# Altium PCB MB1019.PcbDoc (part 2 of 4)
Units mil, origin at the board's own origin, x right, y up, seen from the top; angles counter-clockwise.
Board outline 4655 x 6805 mil, 4 copper layers (TopLayer, VCC, GND, BottomLayer), stack 26.137 mil thick; 557 components, 425 nets, 1918 pads, 817 vias.
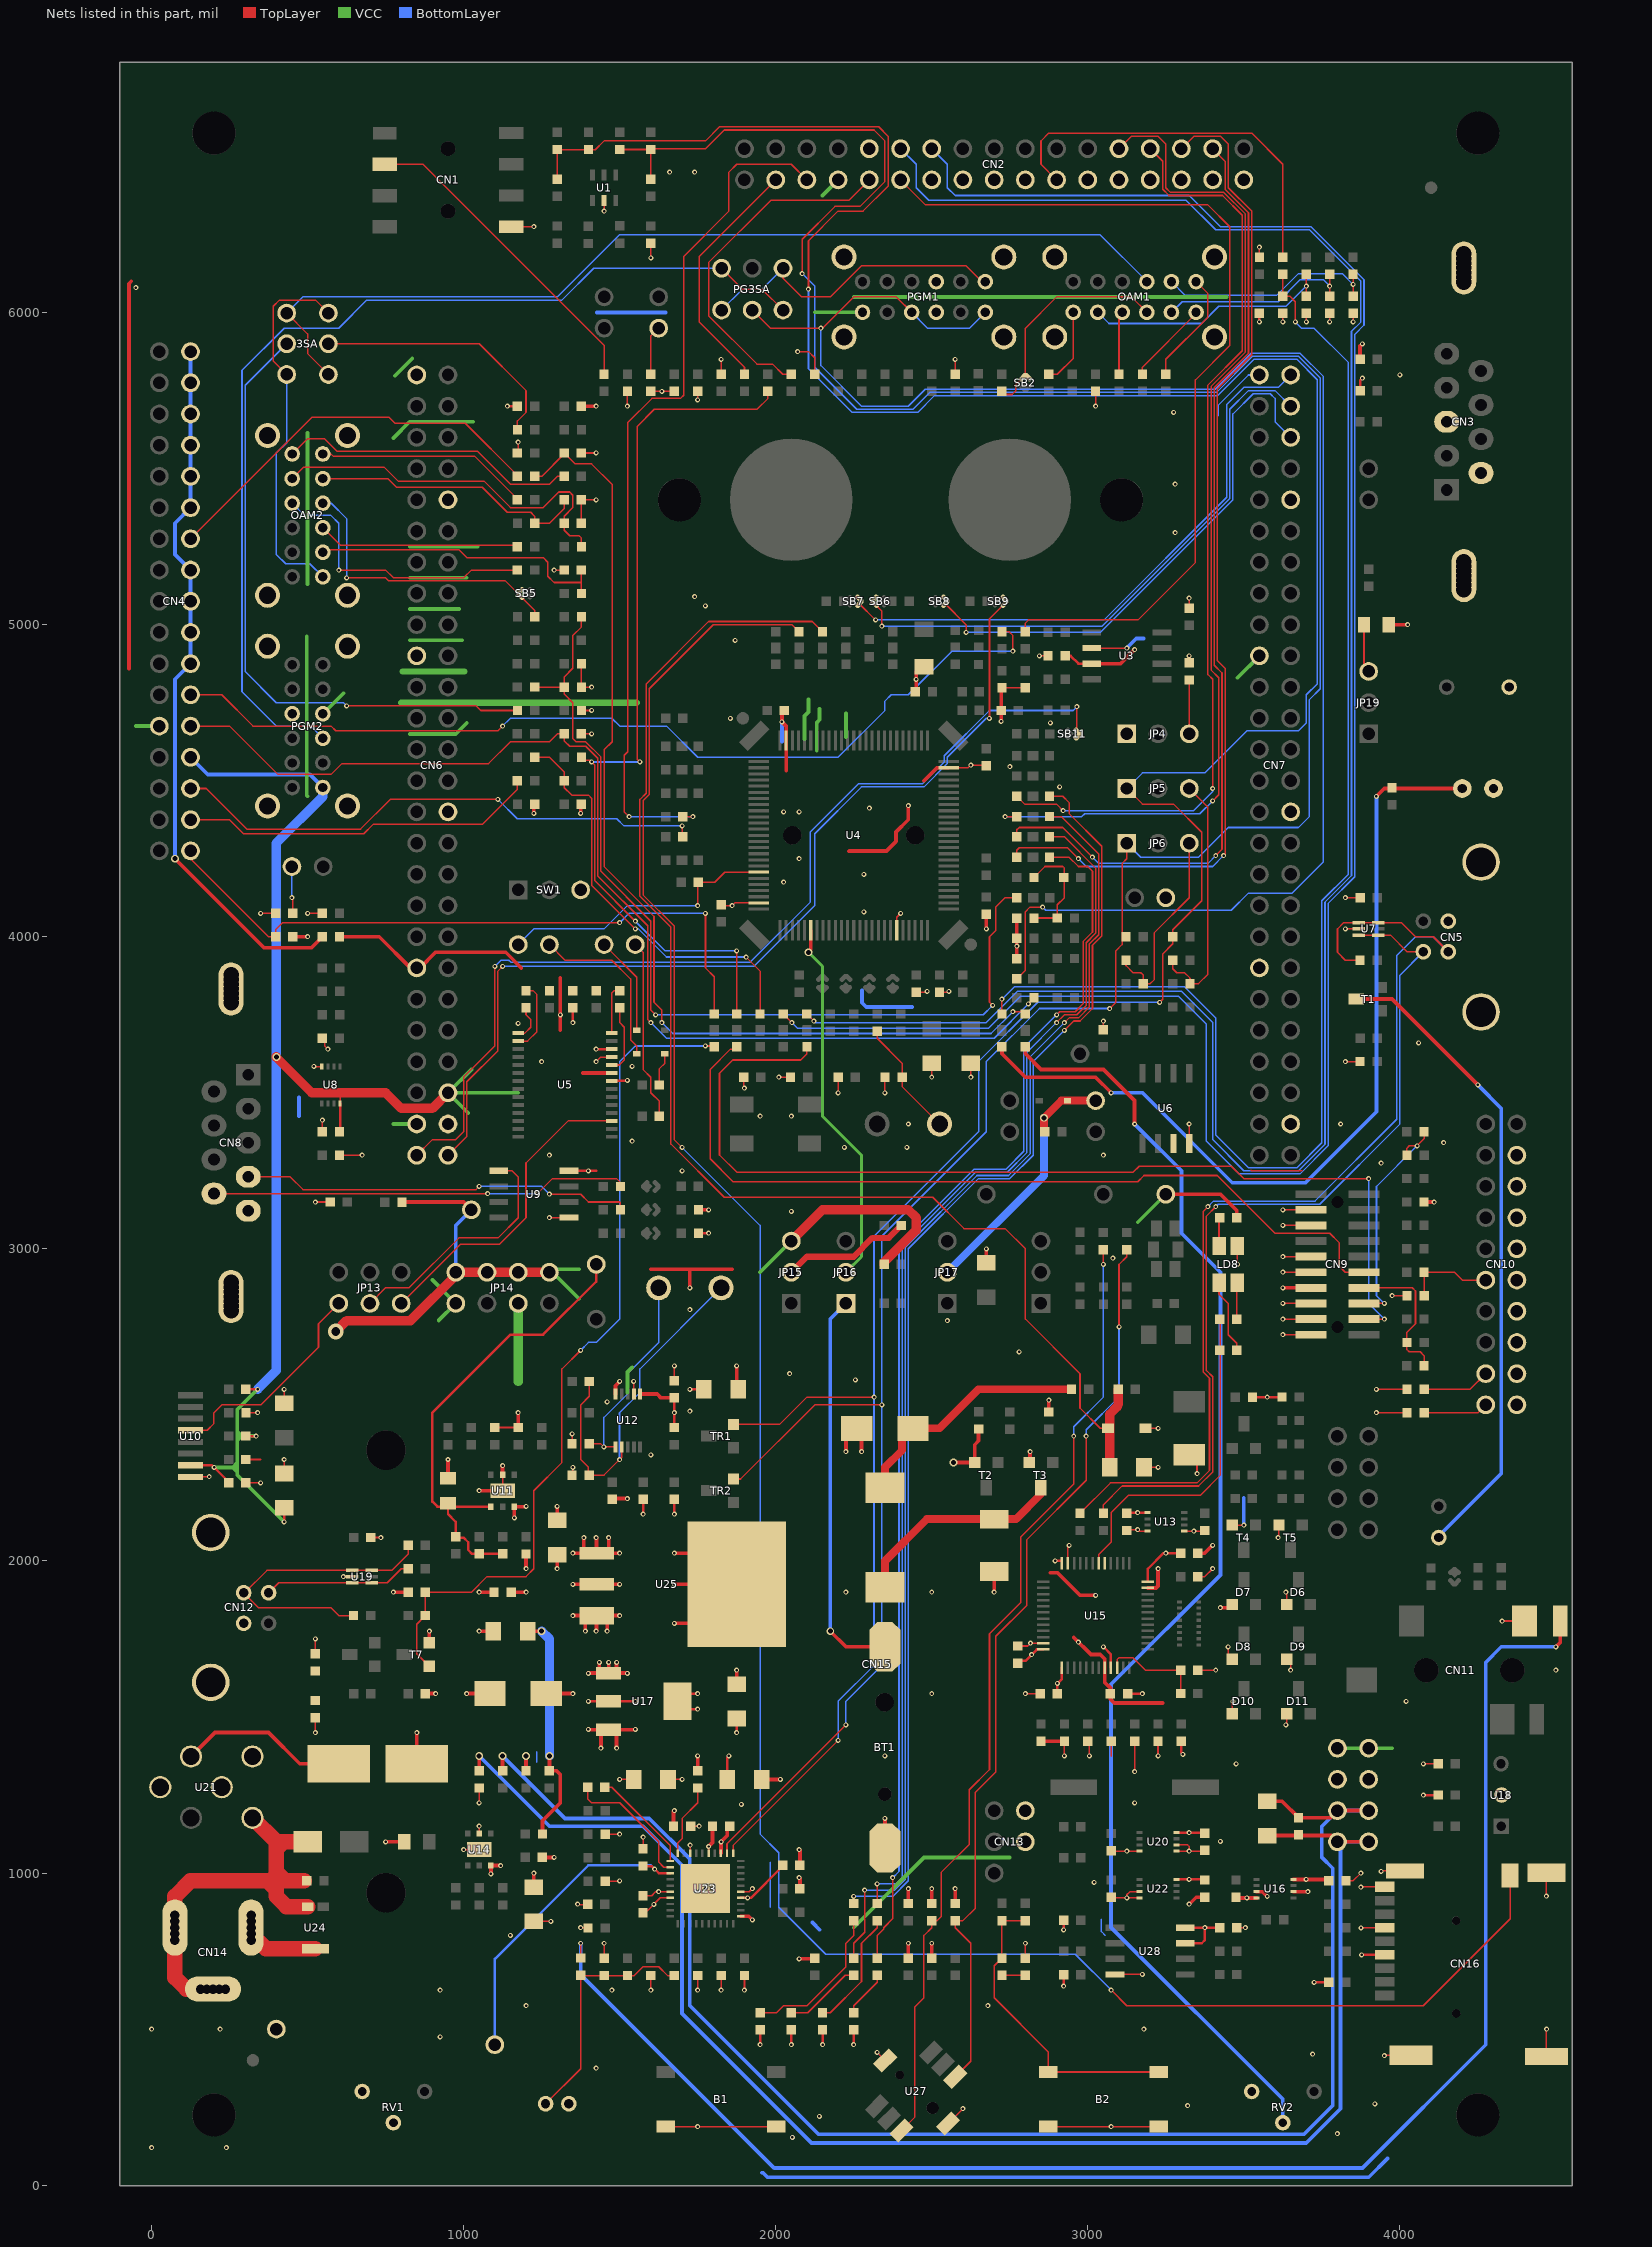
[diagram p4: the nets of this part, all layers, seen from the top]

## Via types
v1: diameter 16, hole 8, TopLayer to BottomLayer, tented both sides, 770 vias
v2: diameter 16, hole 8, TopLayer to BottomLayer, 26 vias
v3: diameter 25, hole 16, TopLayer to BottomLayer, tented both sides, 17 vias
v4: diameter 50, hole 28, TopLayer to BottomLayer, tented both sides, 4 vias

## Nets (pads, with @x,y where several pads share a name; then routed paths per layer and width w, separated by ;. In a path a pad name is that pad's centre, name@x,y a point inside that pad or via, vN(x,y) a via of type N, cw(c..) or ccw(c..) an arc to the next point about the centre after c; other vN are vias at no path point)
+1V8: C66.1 C70.2 R253.2 R278.1 TP6.1 U11.4 | length 1527.4
  TopLayer w7.87: C66.1@950,2173.82 950,2150 975,2125 975,2077.5 977.5,2075 1000,2075 1015,2060 1015,2035 1027.5,2022.5 C70.2@1125,2022.5 ; U11.4@1087.6,2173.82 916.18,2173.82 900,2190 900,2475 1150,2725 1255,2725 1425,2895 TP6.1@1425,2950
+2V5: C96.1 C103.1 C104.1 C105.1 C106.1 TP9.1 U17.2 U23.13 U23.16 U23.34 | length 1686.9
  TopLayer w5: C105.1@1575,927.5 1602.5,927.5 1615.16,940.16 U23.16@1662.01,940.16
  TopLayer w8: v1(1400,1550) v1(1550,1550) ; C106.1@1575,1022.5 1602.5,1022.5 1625.79,999.21 U23.13@1662.01,999.21 ; U17.2@1685,1525 v1(1750,1525) ; U17.2@1685,1575 v1(1750,1575) ; C96.1@1845,1300 1845,1370 v1(1850,1375) ; v1(1875,1450) C104.1@1875,1495 ; U23.34@1887.99,920.47 1920.47,920.47 2022.5,1022.5 C103.1@2022.5,1025
  BottomLayer w8: TP9.1@1100,450 1100,725 1400,1025 1600,1025 v1(1612.32,1012.68)
  other v1: 1910,920.47 1625,940.16
+3V3: C18.2 C36.2 C53.2 C57.1 C60.1 C65.1 C69.1 C74.2 C76.2 C80.2 C82.1 C83.1 C84.2 C86.1 C110.2 C114.1 C115.2 C129.2 CN2.28 CN4.28 CN6.48 CN13.4 CN15.9 CN15.10 CN16.4 JP15.3 LD1.1 LD2.1 LD3.1 LD4.1 LD9.1 PGM1.1 PGM1.4 PGM1.7 PGM2.1 PGM2.4 PGM2.7 R72.2 R78.2 R86.1 R125.2 R222.2 R228.2 R230.2 R240.2 R243.1 R249.2 R252.1 R255.1 R269.1 R270.1 R277.2 R292.2 R293.1 R296.2 R314.1 R320.2 R328.1 T1.3 TP4.1 U3.3 U5.22 U5.26 U8.8 U9.8 U10.7 U12.1 U13.1 U15.1 U15.9 U15.24 U15.36 U15.48 U16.8 U20.8 U22.8 U25.2 U28.7 U28.8 | length 16163.7
  TopLayer w5: U8.8@604.53,3465.94 604.53,3499.53 605,3500
  TopLayer w8: U10.7@125,2306.5 193.5,2306.5 247.5,2252.5 C65.1@247.5,2250 ; R252.1@302.5,2400 v1(335,2400) ; R243.1@302.5,2550 v1(340,2550) ; v1(425,2125) C69.1@425,2170 ; C53.2@604.53,3377.03 U8.8@604.53,3465.94 ; v1(1140,5700) R78.2@1172.5,5700 ; U9.8@1337.5,3250 1425,3250 ; v1(1350,3725) C36.2@1350,3772.5 ; v1@1425.16,3640.16 U5.26@1474.61,3640.16 ; U5.22@1474.61,3537.8 1522.8,3537.8 v1(1525,3540) ; v1@1576,2151 R269.1@1576,2197.5 ; v1(1675,2150) R270.1@1675,2197.5 ; R255.1@1675,2427.5 C60.1@1675,2522.5 ; v1(1725,2550) C57.1@1770,2550 ; R230.2@1752.5,3050 v1(1785,3050) ; v1(1950,450) LD4.1@1950,497.5 ; v1(2050,450) LD3.1@2050,497.5 ; v1(2150,450) LD2.1@2150,497.5 ; v1(2250,450) LD1.1@2250,497.5 ; C80.2@2770,1680 2800,1680 2836.73,1716.73 U15.48@2857.68,1716.73 ; v1(2895,2000) U15.36@2915,2000 ; C82.1@2902.5,1575 v1(2902.5,1607.5) 2916.73,1621.73 U15.1@2916.73,1657.68 ; v1(2922.5,637.5) R328.1@2922.5,674 ; v1(2922.5,817.5) R314.1@2922.5,849 ; C18.2@2927.5,4900 2945,4900 2970,4875 U3.3@3012.5,4875 ; v1(3050,1725) 3074.21,1700.79 U15.9@3074.21,1657.68 ; C76.2@3127.03,2154.53 U13.1@3190.94,2154.53 ; C84.2@3127.5,1575 v1(3175,1575) ; U15.24@3192.32,1933.27 3192.32,1975 3242.32,2025 C74.2@3297.5,2025 ; U22.8@3284.06,979.53 C115.2@3372.97,979.53 ; U20.8@3284.06,1129.53 C110.2@3372.97,1129.53 ; R292.2@3300,1422.5 3300,1385 v1(3305,1380) ; U28.7@3312.5,775 3365,775 3375,785 v1(3375,825) ; U28.8@3312.5,825 C114.1@3422.5,825 ; R249.2@3527.5,2525 R240.2@3622.5,2525 ; v1(3550,5970) R72.2@3550,5997.5 ; v1(3725,650) R320.2@3772.5,650 ; R86.1@3872.5,5750 3872.5,5782.5 v1(3880,5790) ; v1(3877.01,737.99) CN16.4@3951.65,737.99 ; v1(4075,1250) R296.2@4122.5,1250
  TopLayer w12: C86.1@1152.5,1900 v1(1200,1900) ; C83.1@1205,1775 v3(1250,1775) ; R277.2@1252.5,1125 1252.5,1167.5 1310,1225 1310,1315 1297.5,1327.5 1275,1327.5 v3(1275,1375) ; v1(1350,1925) v1(1500,1925) ; U12.1@1565.37,2534.69 1620.31,2534.69 1632.5,2522.5 C60.1@1675,2522.5 ; v1(1675,1800) U25.2@1760,1800 ; v1(1675,1925) U25.2@1780,1925 ; v1(1675,2025) U25.2@1765,2025 ; U3.3@3012.5,4875 3105,4875 v1(3150,4920) ; TP4.1@3250,3175 3425,3175 3477.5,3122.5 R228.2@3477.5,3100 ; R125.2@3325,4877.5 v1(3325,4900) ; U16.8@3659.06,979.53 3767.97,979.53 C129.2@3772.5,975 ; T1.3@3860,3800.5 3974.5,3800.5 v1(4250,3525)
  TopLayer w30: v3(400,3615) 400,3613.54 513.54,3500 750,3500 800,3450 900,3450 CN6.48@950,3500 ; JP15.3@2050,3025 2150,3125 2425,3125 2450,3100 2450,3060 2347.5,2957.5 R222.2@2347.5,2950
  VCC w12: v1(200.24,2299.76) 260.24,2299.76 275,2285 ; 275,2300 260,2300 275,2315 ; 275,2400 290,2400 ; v1(335,2400) 290,2400 ; v1(340,2550) 275,2485 275,2415 ; v1(425,2125) 275,2275 275,2385 ; 497.38,4962.38 497.38,4452.62 500,4450 ; 500,5130 500,5615 ; PGM2.4@549.21,4714.37 614.84,4780 ; 775,5597.91 827.09,5650 1030,5650 ; 780.09,5797.46 835.76,5853.12 ; 827.09,4950 995,4950 ; 827.09,5050 985,5050 ; 827.09,5150 1010,5150 ; 827.09,5250 1045,5250 ; 1015,3435 CN6.48@950,3500 ; 1025,3575 CN6.48@950,3500 ; 1175,3500 CN6.48@950,3500 ; 1950,2925 JP15.3@2050,3025 ; JP15.3@2050,3020 JP15.3@2060,3020 ; 2125.79,6000.79 PGM1.1@2278.15,6000.79 ; 2150,6375 CN2.28@2200,6425 ; 2250,825 2475,1050 2750,1050 ; 2250,6050 3445,6050 ; 3160,3085 TP4.1@3250,3175 ; CN15.9@3800,1400 3975,1400 ; 275,2385 275,2415 ; 275,2385 290,2400 ; 275,2415 290,2400
  BottomLayer w12: CN4.28@125,4575 180,4520 507.36,4520 PGM2.1@549.21,4478.15 ; LD9.1@4125,2075 4120,2075 4325,2280 4325,3450 v1(4250,3525)
  BottomLayer w30: v1(340,2550) 400,2610 400,4300 549.21,4449.21 PGM2.1@549.21,4478.15 ; v3(1250,1775) 1275,1750 v3(1275,1375)
  other v1: 3325,979.53 3325,1129.53 2819.78,1699.78 3250,2025 1575,2150 3160,2154.53 1675,2475 3575,2525 1400,3250 1425,3640
  other v2: 3699.53,979.53
+5V: C67.1 C78.1 C87.1 C91.1 C94.1 C99.1 CN2.25 CN4.25 JP14.2 JP14.4 JP14.6 JP14.8 R225.2 R258.1 R290.1 T3.1 TP5.1 U11.6 U14.6 U17.3 U23.5 U23.8 U25.3 | length 2799.6
  TopLayer w5: R225.2@802.5,3150 R225.2@815,3150 ; C91.1@1655,1300 v1(1700,1300) ; U23.8@1725.79,1062.99 v1(1725.79,1089.21) ; C94.1@1727.5,1150 v1(1755,1150) ; U23.5@1784.84,1062.99 v1@1784.84,1084.84
  TopLayer w12: R225.2@815,3150 1000,3150 TP5.1@1025,3125 ; v1(1087.4,997.6) U14.6@1087.4,1023.82 v1(1118.82,1023.82) ; v1(1162.4,2137.6) U11.6@1162.4,2173.82 v1@1198.82,2173.82 ; R290.1@1200,1327.5 v3(1200,1375) ; C78.1@1225,955 v1(1225,1000) ; C87.1@1265,1575 v1(1350,1575) ; C67.1@1300,2130 v1(1300,2175) ; v1(1350,1825) v1(1500,1825) ; v1(1390,1775) U25.3@1390,1825 ; v1(1400,1460) 1400.55,1459.45 1549.45,1459.45 v1(1550,1460) ; v1(1425,1775) 1426.18,1776.18 U25.3@1426.18,1825 ; v1(1440,1400) U17.3@1440,1459.45 ; v1(1460,1775) U25.3@1460,1825 ; v1(1490,1400) U17.3@1490,1459.45 ; v1(1785,1085) 1797.5,1097.5 C99.1@1797.5,1150 ; T3.1@2815,2315 v1(2815,2350) ; R258.1@2875,2477.5 v1(2875,2515)
  TopLayer w30: v4(590,2735) 625,2770 830,2770 JP14.2@985,2925 ; JP14.2@975,2925 JP14.8@1275,2925
  VCC w12: -50,4675 CN4.25@25,4675 ; JP14.8@1275,2925 1285,2925 1370,2840 ; JP14.8@1275,2935 1370,2935 ; 1525,2540 1525,2605 1540,2620
  BottomLayer w12: JP14.2@975,2925 975,3075 TP5.1@1025,3125
  other v1: 1200,2175
AIN_1: R287.1 R288.2 U15.10 | length 323.9
  TopLayer w5: U15.10@3093.9,1657.68 3093.9,1683.9 3100,1690 3145,1690 3185,1650 3297.5,1650 R288.2@3297.5,1575
BOOT0: JP9.2 R166.1 U4.94 | length 908.4
  TopLayer w5: v1(1750,4100) R166.1@1750,4172.5 ; R166.1@1752.5,4172.5 1752.5,4175 1805,4175 1836.89,4206.89 U4.94@1945.87,4206.89
  BottomLayer w5: JP9.2@1175,3975 1225,4025 1450,4025 1525,4100 v1(1750,4100)
D5V: CN6.49 CN7.19 JP14.1 | length 1852.3
  VCC w12: 775,3400 CN6.49@850,3400 ; 827.09,4650 975,4650 1010,4685 ; 900,2900 JP14.1@975,2825 920,2770 ; 2092.42,4632.58 2092.42,4707.42 2105,4720 2105,4760 ; 2131.89,4596.89 2131.89,4686.89 2140,4695 2140,4730 ; 2225,4640 2225,4715 ; 3480,4830 CN7.19@3550,4900
  VCC w20: 800,4750 1555,4750 ; 805,4850 1002.91,4850
E5V: C85.1 JP14.5 U21.3 | length 824.7
  TopLayer w12: U21.3@126.57,1373.43 203.15,1450 375,1450 475,1350 C85.1@600,1350
  VCC w12: U21.3@126.57,1373.43 U21.3@126.57,1401.57
  VCC w30: 1175,2575 JP14.5@1175,2825
GND: B1.1 B1.4 B2.1 B2.4 BT1.2 C1.1 C2.1 C3.2 C4.1 C5.1 C6.1 C7.1 C8.1 C9.1 C10.1 C11.1 C12.1 C13.1 C14.2 C15.1 C16.1 C17.1 C18.1 C19.1 C20.2 C22.1 C23.1 C24.1 C25.2 C26.1 C27.1 C28.1 C30.2 C31.1 C32.2 C34.1 C35.1 C36.1 C38.1 C39.1 C40.1 C42.2 C43.2 C45.2 C46.2 C47.2 C48.2 C49.1 C50.2 C51.2 C52.1 C53.1 C57.2 C58.2 C59.2 C60.2 C61.2 C62.2 C63.2 C64.2 C65.2 C66.2 C67.2 C68.2 C69.2 C71.2 C72.2 C73.2 C74.1 C75.2 C76.1 C78.2 C79.1 C80.1 C81.2 C82.2 C83.2 C84.1 C85.2 C86.2 C87.2 C88.1 C89.1 C90.2 C91.2 C92.1 C94.2 C95.2 C96.2 C99.2 C103.2 C104.2 C105.2 C106.2 C107.2 C108.1 C109.1 C110.1 C111.1 C112.1 C113.1 C114.2 C115.1 C116.1 C117.2 C118.2 C120.2 C121.1 C122.1 C124.1 C125.1 C126.1 C127.1 C128.1 C129.1 C130.1 C131.2 C132.2 C133.2 C134.2 C135.2 C136.2 CN1.7 CN2.2 CN2.4 CN2.6 CN2.8 CN2.10 CN2.12 CN2.16 CN2.18 CN2.20 CN2.22 CN3.0 CN3.3 CN3.6 CN5.0 CN5.4 CN6.1 CN6.10 CN6.19 CN6.30 CN6.39 CN6.50 CN7.1 CN7.10 CN7.30 CN7.39 CN7.50 CN8.0 CN8.5 CN9.3 CN9.5 CN9.9 CN9.11 CN9.13 CN9.15 CN9.17 CN9.19 CN10.4 CN10.6 CN10.8 CN10.10 CN10.12 CN10.14 CN10.16 CN10.18 CN10.20 CN11.3 CN12.4 CN13.2 CN15.11 CN15.12 CN16.0 CN16.6 CN16.9 D4.1 D5.1 D6.2 D7.2 D8.2 D9.2 D10.2 D11.2 JP4.1 JP8.2 L4.1 LD5.2 LD8.1 OAM1.0 OAM2.0 PGM1.0 PGM2.0 R73.1 R106.2 R112.1 R114.1 R117.1 R130.1 R133.1 R164.1 R214.2 R217.1 R224.1 R226.2 R234.1 R244.2 R251.1 R256.1 R259.1 R261.1 R265.1 R267.2 R268.1 R279.2 R284.2 R287.2 R289.1 R291.1 R294.1 R295.1 R301.1 R302.1 R322.2 R327.1 RV1.2 RV1.3 RV2.3 SW1.3 T2.1 T4.1 T5.1 T7.1 TP8.1 U1.2 U2.2 U3.2 U4.20 U4.49 U4.74 U4.99 U5.23 U5.25 U6.3 U6.4 U7.2 U8.4 U9.5 U10.8 U11.0 U11.2 U12.2 U12.5 U13.4 U13.5 U14.0 U14.2 U15.8 U15.23 U15.35 U15.47 U16.3 U16.4 U16.6 U17.1 U18.2 U19.2 U20.4 U20.5 U20.6 U21.4 U21.5 U21.6 U22.3 U22.4 U23.0 U23.3 U23.17 U23.31 U23.35 U25.1 U26.1 U27.0 U28.4 | length 19223.2
  TopLayer w5: U10.8@125,2269.09 184.09,2269.09 v1(185,2270) ; C65.2@302.5,2250 v1(350,2250) ; C61.2@302.5,2325 350,2325 ; R244.2@302.5,2475 v1(340,2475) ; v1(350,4075) C34.1@397.5,4075 ; C69.2@425,2280 v1(425,2325) ; C62.2@425,2505 v1(425,2550) ; v1(500,4075) C35.1@547.5,4075 ; v1(520,3585) 520.94,3584.06 U8.4@545.47,3584.06 ; v1(525,1450) R289.1@525,1497.5 ; C79.1@525,1702.5 v1(525,1750) ; v1(525,3150) LD5.2@572.5,3150 ; C53.1@547.5,3375 v1(547.5,3412.5) ; C40.1@555,3675 555,3650 v1(565,3640) ; R217.1@602.5,3300 v1(675,3300) ; v1(615,1950) U19.2@643.7,1950 ; C63.2@702.5,2075 v1(735,2075) ; v1(1000,1075) U14.0@1075,1075 ; U14.2@1050,1126.18 v1(1050,1150) ; v1(1050,1225) L4.1@1050,1272.5 ; C58.2@1100,2427.5 C71.2@1175,2427.5 ; U11.0@1125,2225 U11.2@1125,2276.18 ; CN1.7@1152.5,6275 v1(1225,6275) ; C133.2@1175,5552.5 v1(1175,5585) ; C78.2@1225,845 v1(1280,845) ; v1(1275,3100) U9.5@1337.5,3100 ; v1(1290,5175) C17.1@1322.5,5175 ; C59.2@1347.5,2375 v1(1347.5,2407.5) ; C64.2@1350,2277.5 v1(1350,2300) ; v1(1365,900) 1366,899 C112.1@1398.5,899 ; v1(1375,825) 1397.5,825 C111.1@1398.5,824 ; C19.1@1377.5,4650 v1(1410,4650) ; C134.2@1377.5,4725 v1(1410,4725) ; C135.2@1377.5,4875 1377.5,4800 v1(1410,4800) ; C16.1@1377.5,5325 C15.1@1377.5,5400 v1(1425,5400) ; C14.2@1377.5,5550 v1(1425,5550) ; v1(1425,3600) 1439.57,3614.57 U5.25@1474.61,3614.57 ; R322.2@1450,726.5 v1(1450,775) ; v1@1450,6320 U1.2@1450,6358.66 ; R302.1@1453.5,974 1499,974 v1(1500,975) ; R301.1@1453.5,1124 1499,1124 v1(1500,1125) ; v1(1500,1300) C91.2@1545,1300 ; v1(1525,5700) C10.1@1525,5747.5 ; v1(1545,2575) 1545.69,2574.31 U12.2@1545.69,2534.69 ; C105.2@1575,880 1590,880 1630.47,920.47 U23.17@1662.01,920.47 ; C106.2@1575,1077.5 v1(1575,1115) ; v1(1600,625) C118.2@1600,671.5 ; C11.1@1600,5747.5 C12.1@1675,5747.5 ; v1(1600,6175) C1.1@1600,6222.5 ; B1.1@1647.84,187.5 B1.4@2002.16,187.5 ; v1@1672.5,1197.5 v1(1675,1200) ; C60.2@1675,2577.5 v1(1675,2625) ; v1(1750,625) C120.2@1750,671.5 ; v1(1750,5720) C13.1@1750,5747.5 ; v1(1825,625) C128.1@1825,671.5 ; C7.1@1825,5802.5 v1(1825,5850) ; C31.1@1827.5,4100 v1(1860,4100) 1868.47,4108.47 U4.99@1945.87,4108.47 ; U23.35@1887.99,940.16 1915.16,940.16 v1(1925,950) ; C45.2@1897.5,3550 1897.5,3517.5 v1(1900,3515) ; v1(1900,625) C127.1@1900,671.5 ; v1(2010,3550) C50.2@2047.5,3550 ; v1(2070,5875) 2105,5875 2125,5855 C8.1@2125,5802.5 ; v1(2200,3500) C51.2@2200,3550 ; v1(2325,425) U27.0@2351.01,398.99 ; v1(2350,3500) C46.2@2350,3550 ; U4.20@2387.79,4020.87 2387.79,4062.79 v1(2400,4075) ; C38.1@2450,3822.5 2482.5,3822.5 v1(2485,3825) ; v1(2500,3550) C47.2@2500,3595 ; C39.1@2525,3822.5 2552.5,3822.5 v1(2555,3825) ; U27.0@2552.53,197.47 v1(2600,244.94) ; U4.49@2554.13,4541.53 2616.53,4541.53 v1(2625,4550) C25.2@2672.5,4550 ; C132.2@2575,5802.5 v1(2575,5850) ; v1(2625,3550) C48.2@2625,3595 ; C22.1@2722.5,4795 C22.1@2725,4797.5 C23.1@2800,4797.5 ; C80.1@2775,1727.5 2807.5,1727.5 v1(2816.42,1736.42) U15.47@2857.68,1736.42 ; R327.1@2800,727.5 v1(2800,775) ; v1(2800,1575) C82.2@2847.5,1575 ; v1(2845,4900) C18.1@2872.5,4900 ; B2.1@2872.83,187.5 B2.4@3227.17,187.5 ; v1(2925,1375) R291.1@2925,1422.5 ; U15.35@2936.42,1992.32 2936.42,2046.42 v1(2940,2050) ; v1(3005,1375) R295.1@3005,1422.5 ; U3.2@3012.5,4925 v1(3125,4925) ; v1(3025,5700) C131.2@3025,5747.5 ; C49.1@3050,3702.5 v1(3050,3730) ; 3075,1375 C88.1@3075,1422.5 ; C109.1@3076.03,1070.47 U20.4@3165.94,1070.47 ; C113.1@3077.03,920.47 U22.4@3165.94,920.47 ; U28.4@3087.5,675 v1(3175,675) ; v1(3125,920) 3125,930.16 3135,940.16 U22.3@3165.94,940.16 ; C76.1@3127.5,2100 v1(3160,2100) 3164.53,2095.47 U13.4@3190.94,2095.47 ; v1(3150,1325) C89.1@3150,1422.5 ; C68.2@3180,2300 v1(3225,2300) ; D4.1@3185,2425 v1(3225,2425) ; v1(3225,1375) C92.1@3225,1422.5 ; U20.5@3284.06,1070.47 C110.1@3372.97,1070.47 ; U20.6@3284.06,1090.16 3319.84,1090.16 3325,1085 v1(3325,1070.47) ; U13.5@3309.06,2095.47 C72.2@3372.97,2095.47 ; U6.4@3325,3337.5 v1(3325,3400) ; R106.2@3325,5052.5 v1(3325,5085) ; v1(3350,2280) R261.1@3350,2345 ; R287.2@3352.5,1650 v1(3410,1650) ; R279.2@3352.5,1950 3375,1950 v1(3400,1975) ; D8.2@3450,1692.5 v1(3450,1725) ; D10.2@3462.5,1510 3462.5,1547.5 v1(3465,1550) ; T4.1@3462.5,2115 v1(3500,2115) ; C114.2@3477.5,825 v1(3505,825) ; LD8.1@3479.53,3009.06 3479.53,2950.47 v1(3480,2950) ; 3522.27,3252.5 3524.77,3250 3687.5,3250 ; C2.1@3550,6177.5 v1(3550,6210) ; v1(3610,2075) 3612.5,2077.5 T5.1@3612.5,2115 ; v1(3625,2725) CN9.19@3715,2725 ; v1(3625,2775) CN9.17@3715,2775 ; v1(3625,2825) CN9.15@3715,2825 ; v1(3625,2925) CN9.11@3715,2925 ; v1(3625,2975) CN9.9@3715,2975 ; v1(3625,3075) CN9.5@3715,3075 ; v1(3625,3125) CN9.3@3715,3125 ; v1(3625,5970) C3.2@3625,5997.5 ; v1(3635,1475) 3637.5,1477.5 D11.2@3637.5,1510 ; v1(3635,1900) 3637.5,1897.5 D6.2@3637.5,1860 ; v1(3650,1650) D9.2@3650,1682.5 ; v1(3700,5970) C4.1@3700,5997.5 ; v1(3775,5970) C5.1@3775,5997.5 ; v1(3825,3600) R214.2@3872.5,3600 ; v1(3825,4025) U7.2@3868.7,4025 ; v1(3825,4125) C30.2@3872.5,4125 ; C129.1@3827.5,975 3850,975 v2(3875,1000) ; v1(3850,5970) C6.1@3850,5997.5 ; v1(3875,955) 3876.5,956.5 CN16.9@3951.65,956.5 ; v1(3875.39,824.61) CN16.6@3951.65,824.61 ; v1(3925,2475) R259.1@4022.5,2475 ; v1(3925,2550) R251.1@4022.5,2550 ; v1(3940,1005) 3941.69,1006.69 CN16.0@4016.61,1006.69 ; v1(3950,415) 3951.14,416.14 CN16.0@4036.3,416.14 ; v1(3975,2850) R234.1@4022.5,2850 ; v1(4075,1350) C90.2@4122.5,1350 ; v1(4327.48,1807.48) CN11.3@4399.37,1807.48 ; v1(4469.37,925.63) CN16.0@4469.37,1000.79 ; CN16.0@4469.65,412.07 4469.65,499.65 v1(4470,500)
  TopLayer w12: -72.5,4859.19 -72.5,6092.5 -65,6100 ; C28.1@452.5,4000 v1(500,4000) ; R112.1@602.5,4000 730,4000 CN6.39@830,3900 ; v1(750,1100) C75.2@810,1100 ; v1(775,1900) R265.1@822.5,1900 ; C85.2@850,1350 v1(850,1450) ; CN6.39@850,3900 860,3900 910,3950 1135,3950 1185,3900 ; R284.2@877.5,1575 v1(910,1575) ; T7.1@890,1737.5 v1(890,1775) ; C66.2@950,2265 v1(950,2325) ; v1(1010,1575) C87.2@1060,1575 ; v1(1050,1775) C83.2@1095,1775 ; v1(1050,1900) C86.2@1097.5,1900 ; v1(1050,2225) U11.0@1125,2225 ; U11.2@1125,2276.18 v1(1125,2305) ; C71.2@1175,2427.5 v1(1175,2475) ; v1(1200,1975) R267.2@1200,2022.5 ; v1(1225,4395) C27.1@1225,4422.5 ; C73.2@1252.5,1050 v1(1290,1050) ; v1(1300,1975) C67.2@1300,2020 ; 1310,3700 1310,3867.5 ; v1(1350,2025) U25.1@1395,2025 ; v1(1375,4395) C26.1@1375,4422.5 ; C9.1@1377.5,5700 v1(1425,5700) ; 1381.61,3563.39 U5.23@1474.61,3563.39 ; U25.1@1385,2025 v1(1385,2075) ; v1(1400,1640) 1400.55,1640.55 1524.45,1640.55 v1(1525,1640) ; v1(1425,2075) 1426.18,2073.82 U25.1@1426.18,2025 v1(1500,2025) ; U17.1@1435,1640.55 v1(1435,1675) ; U17.1@1465,1640.55 v1(1465,1675) ; U25.1@1465,2025 v1(1465,2075) ; R268.1@1478.5,2200 v1(1525,2200) ; U12.5@1486.63,2534.69 1486.63,2561.63 v1(1500,2575) ; U17.1@1490,1640.55 v1(1490,1675) ; 1600,2935 1860,2935 ; C94.2@1672.5,1150 v1@1672.5,1197.5 ; v1(1725,2875) 1725,2935 ; C95.2@1750,1327.5 v1(1750,1375) ; R226.2@1752.5,3125 v1(1785,3125) ; U23.3@1824.21,1062.99 1825,1063.78 v1(1825,1100) 1845,1120 C99.2@1845,1145 ; C104.2@1875,1605 v1(1875,1650) ; v1(1875,2625) 1875,2555 C57.2@1880,2550 ; U23.31@1887.99,861.42 1913.58,861.42 v1(1925,850) ; C96.2@1955,1300 v1(2015,1300) ; C20.2@2020,4725 v1(2020,4688.46) 2033.46,4675 2033.46,4531.54 ; v1(2075,725) C116.1@2122.5,725 ; v1(2075,985) 2077.5,982.5 C107.2@2077.5,950 ; v1(2075,1075) 2077.5,1072.5 C103.2@2077.5,1025 ; v1(2225,2350) C81.2@2225,2415 ; 2235,4274.08 2235.92,4275 2355,4275 2385.63,4305.63 2385.63,4335.63 2425,4375 v1(2425,4420) ; v1(2275,2350) C81.2@2275,2405 ; BT1.2@2350,1055 v1(2350,1175) ; C126.1@2425,727.5 v1(2425,775) ; C124.1@2425,902.5 v1(2425,950) ; R130.1@2450,4787.5 C52.1@2450,4850 ; 2475,4500 2516.53,4541.53 U4.49@2554.13,4541.53 ; C125.1@2500,727.5 v1(2500,775) ; C122.1@2500,902.5 v1(2500,950) ; v3(2570,2315) T2.1@2637.5,2315 2637.5,2372.5 2650,2385 R256.1@2650,2422.5 ; C108.1@2575,902.5 v1(2575,950) ; C117.2@2675,2955 v1(2675,3000) ; v1(2675,4025) C32.2@2675,4072.5 ; v1(2700,1900) D5.1@2700,1965.94 ; v1(2722.5,4690) C22.1@2722.5,4795 ; R114.1@2772.5,3930 R133.1@2772.5,4060 ; R294.1@2850,1422.5 R291.1@2925,1422.5 ; 2880,1962.2 2902.8,1962.2 2975,1890 v1(3025,1890) ; 2955,1755 3010,1700 3040,1700 3054.53,1685.47 3054.53,1610.47 3072.5,1592.5 3072.5,1557.5 3085,1545 3240,1545 ; U15.23@3192.32,1913.58 3218.58,1913.58 3225,1920 v1(3225,1975) ; v2(3325,900) 3347.5,922.5 C115.1@3375,922.5 ; C74.1@3352.5,2025 3375,2025 v1(3400,2050) ; v1(3425,1850) D7.2@3460,1850 ; C130.1@3477.5,920 U16.4@3540.47,920 ; v2(3510,920) v2@3510,920.47 ; U16.3@3540.94,940.16 3559.84,940.16 v2(3575,925) ; v1(3625,2875) CN9.13@3715,2875 ; U16.6@3659.06,940.16 v2(3704.84,940.16) ; R73.1@3872.5,5850 3872.5,5892.5 v1(3880,5900) ; C121.1@3965,5000 v1(4025,5000) ; R224.1@4077.5,3150 v1(4110,3150)
  BottomLayer w5: 1235,1355 1235,1388.46 ; 1982.5,890 1982.5,1033.82 ; 3043.73,852.17 3043.73,812.43 3056.16,800 ; 3417.5,5670 3417.5,5702.5 3515,5800 CN7.1@3550,5800
  BottomLayer w12: 472.5,3425.86 472.5,3485 ; 1427.09,6000 1647.91,6000 ; 1955,40 1958.67,40 1973.67,25 3900,25 3960,85 ; 2020,4625 v1(2020,4688.46) ; v1(2053.4,152.76) v1@2053.65,152.51 ; 2117.66,841.23 2140.49,818.4 ; 2276.17,3827.83 2276.17,3788.83 2290,3775 2437.5,3775 ; v1@3020,1890 v1(3025,1890) ; v1(3125,4925) 3155.56,4955.56 3178.33,4955.56 ; v1(3500,2115) 3500,2202.5
  other v1: 0,120 240,120 3800,165 1750,187.5 3075,187.5 2140,220 3320,255 3920,260 1425,375 3720,420 925,475 0,500 220,500 3180,500 1200,575 2680,575 925,625 1475,625 1150,800 1609.86,899.86 1775,950 3125,1070.47 1890,1220 3150,1225 3475,1350 2350,1375 2500,1575 2970,1740 2225,1900 2500,1900 3340,2095.47 1600,2340 1725,2480 1460,2510 2255,2580 2045,2600 2780,2670 1725,2805 3080,2970 2050,3120 1700,3250 3940,3275 1275,3300 2220,3325 2420,3325 4140,3340 1540,3345 2425,3400 3810,3400 1950,3425 2050,3425 1540,3585 1250,3600 4060,3660 1175,3722.24 1310,3750 2772.5,3970 2282.5,4080 2025,4175 2282.5,4200 2075,4250 2025,4400 2075,4400 2300,4412.5 2910,4480 2750,4545 2880,4685 1855,4700 2450,4825 1870,4950 1775,5060 1740,5090 3280,5295 3280,5450 3275,5680 1635,5747.5 4000,5800 -50,6080 1450,6325 1660,6450 1740,6450
  other v2: 3020,970 3425.01,1101.1 4020,1550 4500,1650 2550,2770 3050,3300
LED_STLINK: R236.1 R239.1 U15.30 | length 1076.5
  TopLayer w5: U15.30@3034.84,1992.32 3034.84,2020.7 3075,2060.86 3075,2155 3130,2210 3360,2210 3425,2275 R236.1@3425,2772.5
MC1_CURRENTA+: C4.2 OAM1.2 R68.2 | length 802.6
  TopLayer w5: C4.2@3700,6052.5 R68.2@3700,6122.5
  BottomLayer w5: OAM1.2@3031.89,6000.79 3067.68,5965 3365,5965 3420,6020 3635,6020 v1(3700,6085)
MC1_CURRENTB+: C5.2 OAM1.5 R69.2 | length 628.3
  TopLayer w5: C5.2@3775,6052.5 R69.2@3775,6122.5
  BottomLayer w5: OAM1.5@3268.11,6000.79 3302.32,6035 3610,6035 3680,6105 3755,6105 v1(3775,6085)
MC1_CURRENTC+: C6.2 OAM1.8 R70.2 | length 713.7
  TopLayer w5: C6.2@3850,6052.5 R70.2@3850,6122.5
  BottomLayer w5: OAM1.8@3268.11,6099.21 3312.32,6055 3605,6055 3675,6125 3815,6125 v1(3850,6090)
MC1_MC2_PFCPWM: R3.1 R145.2 R148.2 | length 1336.4
  TopLayer w5: R145.2@1227.5,4575 1275,4575 1322.5,4527.5 1322.5,4477.5 1346.15,4453.85 1400,4453.85 1410,4443.85 1410,4165 v1(1550,4025) ; v1(1905,3935) 1950,3890 R3.1@1950,3752.5
  BottomLayer w5: v1(1550,4025) 1560,4025 1650,3935 v1(1905,3935)
MC1_MC2_PFCSYNC: R1.1 R81.2 R147.2 | length 2884.6
  TopLayer w5: R147.2@1375,4565 1405,4565 1420,4550 1420,4180 v1(1550,4050) ; v1(1565,4560) 1556,4569 1556,5635.29 1610.71,5690 1940,5690 1975,5725 R81.2@1975,5747.5 ; R1.1@1875,3752.5 v1(1875,3955)
  BottomLayer w5: v1(1410,4560) v1(1565,4560) ; v1(1550,4050) 1645,3955 v1(1875,3955)
MC2_CURRENTA+: C16.2 OAM2.8 R99.2 | length 1209.9
  TopLayer w5: OAM2.8@450.79,5468.11 487.68,5505 745,5505 790,5460 1065,5460 1150,5375 1255,5375 1305,5425 1340,5425 1350,5415 1350,5375 1322.5,5347.5 1322.5,5302.5 1340,5285 1370,5285 1377.5,5277.5 R99.2@1377.5,5250
MC2_CURRENTB+: C15.2 OAM2.5 R97.2 | length 892.9
  TopLayer w5: OAM2.5@549.21,5468.11 756.89,5468.11 785,5440 1060,5440 1140,5360 1215,5360 1227.5,5347.5 1227.5,5325 1275,5325 1322.5,5372.5 C15.2@1322.5,5400
MC2_CURRENTC+: C17.2 OAM2.2 R101.2 | length 979.2
  TopLayer w5: OAM2.2@557.32,5240 985,5240 1010,5215 1255,5215 1270,5200 1270,5155 1290,5135 1377.5,5135 ; R101.2@1377.5,5100 C17.2@1377.5,5175 ; 1377.5,5130 1372.5,5135 1377.5,5140
MCO: U15.29
Net3SA_2: 3SA.2 R90.1 | length 831.6
  TopLayer w5: 3SA.2@566.93,5900 1050,5900 1200,5750 1200,5680 1172.5,5652.5 R90.1@1172.5,5625
Net3SA_5: 3SA.5 R138.1 | length 2029.4
  TopLayer w5: v1(625,4740) 1040,4740 1055,4725 R138.1@1172.5,4725
  BottomLayer w5: 3SA.5@433.07,5900 300,5766.93 300,4850 400,4750 615,4750 v1(625,4740)
NetB2_2: B2.2 B2.3 C123.2 R312.1 R313.1 | length 996.3
  TopLayer w5: R312.1@2800,847.5 2725,847.5 C123.2@2725,727.5 2700,702.5 2700,600 2872.83,427.17 B2.2@2872.83,362.5 B2.3@3227.17,362.5
NetBT1_1: BT1.1 JP16.1 | length 1266.4
  TopLayer w12: v3(2175,1775) 2225,1725 BT1.1@2350,1725
  BottomLayer w12: v3(2175,1775) 2175,2775 JP16.1@2225,2825
NetC11_2: C11.2 JP2.2 | length 157.9
  TopLayer w5: C11.2@1600,5802.5 1600,5925 JP2.2@1625,5950
NetC34_2: C34.2 JP7.2 | length 151
  TopLayer w5: v1(450,4125) 452.5,4122.5 C34.2@452.5,4075
  BottomLayer w5: v1(450,4125) JP7.2@450,4225
NetC41_1: C41.1 U5.1 | length 116
  TopLayer w5: U5.1@1175.39,3691.34 1196.34,3691.34 1215,3710 1215,3735 1200,3750 C41.1@1200,3772.5
NetC41_2: C41.2 U5.2 | length 231.5
  TopLayer w5: U5.2@1175.39,3665.75 1205,3665.75 1235,3695.75 1235,3815 1222.5,3827.5 C41.2@1200,3827.5
NetC44_1: C44.1 U5.24 | length 220.7
  TopLayer w5: U5.24@1474.61,3588.98 1498.98,3588.98 1515,3605 1515,3710 1500,3725 C44.1@1500,3772.5
NetC44_2: C44.2 U5.28 | length 156.9
  TopLayer w5: U5.28@1474.61,3691.34 1474.61,3819.61 1482.5,3827.5 C44.2@1500,3827.5
NetC46_1: C46.1 R205.2 X2.1 | length 380.3
  TopLayer w5: R205.2@2325,3697.5 2325,3675 2405,3595 2405,3520 X2.1@2525,3400
NetC59_1: C59.1 U12.6 X3.2 | length 705.8
  TopLayer w5: C59.1@1402.5,2375 1440,2375 v1(1449.69,2365.31) U12.6@1486.63,2365.31 ; X3.2@1600,2850 X3.2@1625,2875
  BottomLayer w5: v1(1449.69,2365.31) 1449.69,2459.69 1525,2535 1525,2600 1625,2700 X3.2@1625,2875
NetC64_1: C64.1 R237.2 U12.7 X3.1 | length 1169.2
  TopLayer w5: R237.2@1402.5,2575 1402.5,2527.5 1375,2500 1375,2325 1400,2300 1400,2277.5 C64.1@1402.5,2275 1450,2275 1506.31,2331.32 U12.7@1506.31,2365.31
  BottomLayer w5: v1(1499.54,2324.54) 1499.54,2474.54 1565,2540 1565,2615 X3.1@1825,2875
NetC79_2: C79.2 CN12.0 R289.2
NetC93_1: C93.1 U23.12 | length 430.6
  TopLayer w5: C93.1@1397.5,1275 1397.5,1237.5 1410,1225 1500,1225 1625,1100 1625,1035 1641.1,1018.9 U23.12@1662.01,1018.9
NetC93_2: C93.2 U23.11 | length 336.4
  TopLayer w5: C93.2@1452.5,1275 1475,1275 1662.01,1087.99 U23.11@1662.01,1038.58
NetC95_1: C95.1 U23.10 | length 235.8
  TopLayer w5: U23.10@1686.42,1062.99 1686.42,1096.42 1700,1110 1700,1175 1750,1225 C95.1@1750,1272.5
NetC119_2: C119.2 R321.1 R322.1 R323.1 U26.2 | length 782.5
  TopLayer w5: U26.2@1262.6,260.63 1375,373.03 1375,672.5 1376,671.5 1546.5,671.5 1575,700 1625,700 1653.5,671.5 C119.2@1675,671.5
NetC123_1: C123.1 R327.2 | length 75
  TopLayer w5: C123.1@2725,672.5 R327.2@2800,672.5
NetCN1_4: CN1.4 R136.2 | length 1035.2
  TopLayer w5: CN1.4@747.5,6475 870,6475 1450,5895 R136.2@1450,5802.5
NetCN2_14: CN2.14 R67.2 | length 1270
  TopLayer w5: CN2.14@2900,6425 2850,6475 2850,6550 2875,6575 3525,6575 3625,6475 R67.2@3625,6177.5
NetCN2_24: CN2.24 R119.2 | length 2891.5
  TopLayer w5: CN2.24@2400,6425 2480,6345 3385,6345 3455,6275 3455,5894.14 3345,5784.14 3345,5199.14 3160.86,5015 2810,5015 2800,5005 R119.2@2800,4977.5
NetCN2_26: CN2.26 R82.1 | length 1137.4
  TopLayer w5: R82.1@2050,5802.5 2022.5,5802.5 1990,5835 1940,5835 1785,5990 1785,6160 1985,6360 2235,6360 CN2.26@2300,6425
NetCN2_30: CN2.30 R153.2 | length 2807.3
  TopLayer w5: v1(1530,4385) 1515,4400 1515,4581.72 1526,4592.72 1526,5647.72 1603.28,5725 1695,5725 1705,5735 1705,6180 1850,6325 1850,6450 1875,6475 2050,6475 CN2.30@2100,6425 CN2.30@2100,6400 ; R153.2@1702.5,4385 v1(1735,4385)
  BottomLayer w5: v1(1530,4385) v1(1735,4385)
NetCN2_32: CN2.32 R80.2 | length 784
  TopLayer w5: R80.2@1900,5802.5 1900,5825 1755,5970 1755,6180 CN2.32@2000,6425
NetCN4_2: CN4.2 CN4.4 CN4.6 CN4.8 CN4.10 CN4.12 CN4.16 CN4.18 CN4.20 CN4.22 R112.2 | length 2292.2
  TopLayer w12: v3(75,4250) 360,3965 512.5,3965 R112.2@547.5,4000
  BottomLayer w12: v3(75,4250) 75,4825 CN4.22@125,4875 CN4.16@125,5175 75,5225 75,5325 CN4.12@125,5375 CN4.2@125,5875
NetCN4_14: CN4.14 R91.2 | length 1286.7
  TopLayer w5: CN4.14@125,5275 515,5665 760,5665 780,5645 1005,5645 R91.2@1172.5,5477.5
NetCN4_24: CN4.24 R123.2 | length 2999.6
  TopLayer w5: CN4.24@125,4775 225,4775 325,4675 575,4675 590,4660 1110,4660 v1(1125,4675) ; R123.2@2725,4977.5 2747.5,4977.5 2760,4965 v1(2760,4915)
  BottomLayer w5: v1(1125,4675) 1150,4700 1475,4700 1500,4675 1650,4675 1750,4575 2200,4575 2350,4725 2350,4755 2370,4775 2425,4775 2565,4915 v1(2760,4915)
NetCN4_30: CN4.30 R165.2 | length 1740.9
  TopLayer w5: CN4.30@125,4475 175,4475 305,4345 670,4345 765,4440 v1(1110,4440) ; R165.2@1700,4317.5 v1(1700,4355)
  BottomLayer w5: v1(1110,4440) 1171.89,4378.11 1491.03,4378.11 1514.14,4355 v1(1700,4355)
NetCN4_32: CN4.32 R146.2 | length 1152.7
  TopLayer w5: CN4.32@125,4375 250,4375 295,4330 680,4330 710,4360 1060,4360 1172.5,4472.5 R146.2@1172.5,4500
NetCN5_2: CN5.2 R274.2 U7.3 U7.4 | length 2802.9
  TopLayer w5: R274.2@3050,2152.5 3050,2180 3110,2240 3355,2240 3400,2285 3400,2590 3380,2610 3380,3105 v1(3410,3135) ; U7.3@3868.7,4005.32 3969.68,4005.32 4023,3952 CN5.2@4075,3952
  BottomLayer w5: v1(3410,3135) 3418.14,3143.14 3743.14,3143.14 4000,3400 4000,3877 CN5.2@4075,3952
NetCN5_3: CN5.3 R185.2 R273.2 U7.1 U7.6 | length 3346.6
  TopLayer w5: R273.2@2975,2152.5 3072.5,2250 3350,2250 3390,2290 3390,2585 3370,2605 3370,3120 v1(3385,3135) ; R185.2@3872.5,3925 3825,3925 3800,3950 3800,4025 3819.68,4044.68 4005.32,4044.68 4050,4000 4107,4000 CN5.3@4155,3952
  BottomLayer w5: v1(3385,3135) 3403.14,3153.14 3728.14,3153.14 3990,3415 3990,3940 4050,4000 4107,4000 CN5.3@4155,3952
NetCN6_51: CN6.51 SB11.1 | length 3191
  TopLayer w5: CN6.51@850,3300 900,3350 975,3350 1000,3375 1000,3550 1100,3650 v1(1100,3905) ; v1(2965,4737) 2965,4661 SB11.1@2968,4658
  BottomLayer w5: v1(1100,3905) 1120,3925 1145,3925 1151.22,3918.78 1918.78,3918.78 2110,4110 2110,4335 2265,4490 2470,4490 2540,4560 2540,4580 2685,4725 2953,4725 v1(2965,4737)
NetCN6_52: CN6.52 SB9.1 | length 3100.1
  TopLayer w5: CN6.52@950,3300 1010,3360 1010,3535 1110,3635 1110,3890 v1(1125,3905) ; v1(2685,4700) 2685,5019 SB9.1@2733,5067
  BottomLayer w5: v1(1125,3905) 1930,3905 2125,4100 2125,4330 2275,4480 2475,4480 2550,4555 2550,4575 2675,4700 v1(2685,4700)
NetCN7_2: CN7.2 SB7.1 | length 1902.5
  TopLayer w5: SB7.1@2268,5067 v1(2320,5015)
  BottomLayer w5: v1(2320,5015) 3051.72,5015 3445,5408.28 3445,5705 3500,5760 3610,5760 CN7.2@3650,5800
NetCN7_4: CN7.4 SB6.1 | length 1892.4
  TopLayer w5: SB6.1@2317,5067 2340,5044 v1(2340,4995)
  BottomLayer w5: v1(2340,4995) 3045.86,4995 3455,5404.14 3455,5690 3515,5750 3600,5750 CN7.4@3650,5700
NetCN7_6: CN7.6 SB8.1 | length 1739.6
  TopLayer w5: SB8.1@2543,5067 2610,5000 v1(2610,4975)
  BottomLayer w5: v1(2610,4975) 3040,4975 3465,5400 3465,5675 3530,5740 3585,5740 3600,5725 3600,5650 CN7.6@3650,5600
NetCN8_4: CN8.4 R219.2 | length 1257.9
  TopLayer w5: CN8.4@310,3231 444,3231 485,3190 1040,3190 v1(1050,3200) ; v1(1275,3175) 1375,3175 1400,3150 1500,3150 1502.5,3147.5 R219.2@1502.5,3125
  BottomLayer w5: v1(1050,3200) 1250,3200 v1(1275,3175)
NetCN8_9: CN8.9 R220.2 | length 1340.1
  TopLayer w5: CN8.9@200,3177 v1(1077,3177) ; v1(1237,3177) 1285,3225 1490,3225 1502.5,3212.5 R220.2@1502.5,3200
  BottomLayer w5: v1(1077,3177) v1(1237,3177)
NetCN9_12: CN9.12 R2.1 | length 2704.6
  TopLayer w5: R2.1@1875,3640 1855,3640 1790,3575 1790,3288.28 1863.28,3215 3160,3215 3180,3235 3415,3235 3600,3050 3775,3050 3805,3020 3805,2945 3825,2925 CN9.12@3885,2925
NetCN9_14: CN9.14 R241.1 R242.1 | length 463.8
  TopLayer w5: CN9.14@3885,2875 4040,2875 4050,2865 4050,2760 4022.5,2732.5 4022.5,2677.5 4030,2670 4065,2670 4077.5,2657.5 R242.1@4077.5,2625
NetCN9_16: CN9.16 R216.1 R223.1 | length 736.6
  TopLayer w5: CN9.16@3885,2825 v1(3950,2825) ; R223.1@4022.5,3300 4022.5,3322.5 4030,3330 v1(4055,3330) 4077.5,3352.5 R216.1@4077.5,3365
  BottomLayer w5: v1(3950,2825) 3925,2850 3925,3200 v1(4055,3330)
NetCN9_18: CN9.18 R8.1 | length 3288.9
  TopLayer w5: R8.1@2100,3647.5 2100,3625 2080,3605 1862.43,3605 1820,3562.57 1820,3300.71 1875.71,3245 3145,3245 3165,3265 3460,3265 3500,3225 v1(3900,3225) ; CN9.18@3840,2775 CN9.18@3875,2775 ; CN9.18@3885,2775 v1(3950,2775)
  BottomLayer w5: v1(3900,3225) 3900,2825 v1(3950,2775)
NetCN10_11: CN10.11 R232.1 R234.2 | length 282.9
  TopLayer w5: R234.2@4077.5,2850 4077.5,2925 4175,2925 4200,2900 CN10.11@4275,2900
NetCN10_17: CN10.17 R251.2 | length 218.2
  TopLayer w5: R251.2@4077.5,2550 4225,2550 CN10.17@4275,2600
NetCN10_19: CN10.19 R259.2 | length 207.9
  TopLayer w5: R259.2@4077.5,2475 4250,2475 CN10.19@4275,2500
NetCN11_2: CN11.2 R321.2 | length 5026.7
  TopLayer w5: R321.2@1375,727.5 v1(1375,775)
  TopLayer w12: v1(4500,1725) 4513.54,1738.54 CN11.2@4513.54,1807.48
  BottomLayer w12: v1(1375,775) 1375,675 1995,55 3880,55 4275,450 4275,1675 4325,1725 v1(4500,1725)
NetCN12_2: CN12.2 R266.2 U19.3 U19.4 | length 479.4
  TopLayer w5: CN12.2@375,1898 407.31,1930.31 755.31,1930.31 800,1975 R266.2@822.5,1975
NetCN12_3: CN12.3 R260.2 R272.2 U19.1 U19.6 | length 986.4
  TopLayer w5: CN12.3@295,1898 343,1850 575,1850 600,1825 R272.2@647.5,1825 ; CN12.3@298,1898 369.69,1969.69 575,1969.69 ; 575,1970 575.31,1969.69 769.69,1969.69 822.5,2022.5 R260.2@822.5,2050
NetCN14_1: CN14.1 U24.1 | length 225.6
  TopLayer w50: CN14.1@319.09,805 366.59,757.5 U24.1@525,757.5
NetCN14_3: C97.2 CN14.2 CN14.3 U21.2 U24.2 Z1.1 | length 1439.7
  TopLayer w12: 360,960 390,930 ; 365,985 400,1020 ; 410,1060 435,1085 ; 415,1015 445,985
  TopLayer w50: CN14.3@75,785 75,665 111.85,628.15 CN14.2@217.05,628.15 ; CN14.3@75,865 75,925 125,975 C97.2@490,975 ; U21.2@323.43,1176.57 400,1100 ; U24.2@500,892.5 432.5,892.5 400,925 400,1100 ; Z1.1@500.2,1100 400,1100
NetCN16_10: CN16.10 R48.1 | length 7395.4
  TopLayer w5: v1(1700,3325) 1674.31,3350.69 1674.31,4034.83 1575,4134.14 1575,4435.86 1595,4455.86 1595,4795 1800,5000 2052.5,5000 R48.1@2075,4977.5 ; v1(3075,625) 3125,575 4075,575 4353.23,853.23 CN16.10@4353.23,991.93
  BottomLayer w5: v1(1700,3325) 1950,3075 1950,1125 2010,1065 2010,890 2160,740 2960,740 v1(3075,625)
NetD2_1: D2.1 R202.1 | length 107.2
  TopLayer w5: R202.1@1627.5,3525 1627.5,3577.5 1645,3595 D2.1@1645,3625
NetD4_2: C68.1 D4.2 R46.1 R248.1 | length 4410.6
  TopLayer w5: R46.1@2150,4977.5 2117.5,5010 1785,5010 1585,4810 1585,4460 1565,4440 1565,4130 1664.31,4030.69 1664.31,3335.69 1835,3165 2503.43,3165 2603.43,3065 2735,3065 2800,3000 2800,2775 2975,2600 2975,2490 3040,2425 D4.2@3065,2425
  TopLayer w30: C68.1@3070,2300 3070,2470 3093.96,2493.96 ; 3097.5,2502.5 R248.1@3097.5,2550
NetD5_2: D5.2 L2.1 T3.3 | length 693.9
  TopLayer w25: L2.1@2350,1915.55 2350,2000 2484.06,2134.06 2770,2134.06 2849.5,2213.56 T3.3@2849.5,2235
NetJP4_3: JP4.3 R125.1 | length 172.5
  TopLayer w5: JP4.3@3325,4650 R125.1@3325,4822.5
NetJP5_1: JP5.1 R59.1 R60.1 R63.1 R183.1 TR1.1 U23.1 | length 10564.2
  TopLayer w5: R63.1@1300,6427.5 1300,6522.5 1301,6521.5 1421.5,6521.5 1450,6550 1775,6550 1820,6595 2330,6595 2360,6565 2360,6405 2280,6325 2200,6325 2105,6230 v1(2105,6075) ; U23.1@1863.58,1062.99 1863.58,1088.58 v1(2200,1425) ; TR1.1@1865,2437.5 2012.5,2437.5 2100,2525 v1(2315,2525) ; JP5.1@3125,4475 3175,4425 3275,4425 3365,4335 3365,4115 3272.5,4022.5 3272.5,3977.5 3240,3945 3240,3800 v1(3230,3790)
  BottomLayer w5: v1(2105,6075) 2105,5820 2245,5680 2455,5680 2509,5734 3416.28,5734 3532.28,5850 3670,5850 3735,5785 3735,4810 3700,4775 3700,4685 3675,4660 3510,4660 3375,4525 3175,4525 JP5.1@3125,4475 ; v1(2200,1425) 2200,1550 2315,1665 2315,3040 2650,3375 2650,3600 2840,3790 v1(3230,3790)
NetJP5_3: JP5.3 R182.1 R184.2 | length 802.2
  TopLayer w5: R182.1@3272.5,3925 3272.5,3897.5 3285,3885 3310,3885 3327.5,3867.5 3327.5,3850 3355,3850 3385,3880 3385,4415 JP5.3@3325,4475
NetJP6_1: JP6.1 R61.1 R62.1 R64.1 R180.1 TR2.1 U23.2 | length 10208.7
  TopLayer w5: R61.1@1500,6522.5 R62.1@1600,6522.5 ; R64.1@1600,6427.5 R62.1@1600,6522.5 ; U23.2@1843.9,1062.99 1843.9,1093.9 v1(2225,1475) ; TR2.1@1865,2262.5 1887.5,2262.5 2125,2500 v1(2340,2500) ; v1(2085,6125) 2085,6235 2190,6340 2270,6340 2350,6420 2350,6550 2315,6585 1835,6585 1775,6525 1602.5,6525 R62.1@1600,6522.5 ; v1(3070,3770) 3090,3790 3090,3955 3110,3975 3110,4235 3125,4250 JP6.1@3125,4300
  BottomLayer w5: v1(2085,6125) 2125,6085 2125,5825 2260,5690 2440,5690 2494,5744 3412.14,5744 3528.14,5860 3675,5860 3745,5790 3745,4795 3710,4760 3710,4385 3675,4350 3450,4350 3355,4255 3170,4255 JP6.1@3125,4300 ; v1(2225,1475) 2225,1550 2340,1665 2340,3040 2675,3375 2675,3600 2845,3770 v1(3070,3770)
NetJP6_3: JP6.3 R179.1 R181.2 | length 636.7
  TopLayer w5: R179.1@3122.5,3925 3122.5,3907.5 3145,3885 3170,3885 3177.5,3877.5 3177.5,3850 3200,3850 3213.39,3863.39 3213.39,4013.39 3325,4125 JP6.3@3325,4300
NetJP9_1: D2.2 JP9.1 | length 553.8
  TopLayer w5: JP9.1@1275,3975 1325,3925 1475,3925 1535,3865 1535,3670 1555,3650 D2.2@1555,3625
NetJP10_1: D1.2 JP10.1 | length 318.5
  TopLayer w5: JP10.1@1450,3975 1555,3870 D1.2@1555,3700
NetJP10_2: JP10.2 R215.1 | length 582.1
  TopLayer w5: JP10.2@1550,3975 1575,3950 1575,3575 1600,3550 1600,3500 1627.5,3472.5 R215.1@1627.5,3425
NetJP13_1: JP13.1 U10.4 | length 707.7
  TopLayer w5: U10.4@125,2418.7 178.7,2418.7 200,2440 200,2475 225,2500 350,2500 535,2685 535,2760 JP13.1@600,2825
NetJP13_3: JP13.3 U9.1 | length 789.7
  TopLayer w5: JP13.3@700,2825 750,2875 825,2875 985,3035 1110,3035 1175,3100 1175,3230 1155,3250 U9.1@1112.5,3250
NetJP13_5: JP13.5 U5.17 | length 1019.4
  TopLayer w5: JP13.5@800,2825 990,3015 1115,3015 1200,3100 1200,3275 1334.84,3409.84 U5.17@1474.61,3409.84
NetJP15_2: JP15.2 R227.2 | length 417.1
  TopLayer w12: R227.2@2400,3075 R227.2@2402.5,3075
  TopLayer w20: JP15.2@2050,2925 2100,2975 2250,2975 2310,3035 2362.5,3035 R227.2@2402.5,3075
NetJP16_2: JP16.2 U4.6 | length 1190
  TopLayer w10: v3(2105,3950) 2112.2,3957.2 U4.6@2112.2,4020.87
  VCC w10: v3(2105,3950) 2150,3905 2150,3425 2275,3300 2275,2975 JP16.2@2225,2925
NetJP17_2: D3.2 JP11.2 JP17.2 L1.1 | length 843.7
  TopLayer w25: L1.1@2860,3377.5 v3(2860,3420) 2915,3475 JP11.2@3015,3475
  BottomLayer w25: JP17.2@2550,2925 2860,3235 v3(2860,3420)
NetJP19_3: C121.2 JP19.3 | length 156.2
  TopLayer w5: C121.2@3885,5000 3885,4865 JP19.3@3900,4850
NetL2_2: C81.1 L2.2 R238.1 | length 757.6
  TopLayer w25: L2.2@2350,2234.45 2350,2300 2405,2355 C81.1@2405,2420 ; C81.1@2450,2425 2525,2425 2650,2550 R238.1@2947.5,2550
NetL3_2: C100.1 C101.1 CN15.13 CN15.14 L3.2 | length 4959.1
  TopLayer w12: L3.2@1125,1327.5 v3(1125,1375) ; C100.1@3575,1230 3622.5,1230 C101.1@3675,1177.5 3777.5,1177.5 CN15.13@3800,1200 CN15.14@3900,1200
  BottomLayer w12: v3(1125,1375) 1325,1175 1595,1175 1725,1045 1725,575 2136.82,163.18 3693.18,163.18 3785,255 3785,1015 3750,1050 3750,1150 CN15.13@3800,1200 CN15.14@3900,1200
NetL4_2: C100.2 C101.2 CN15.15 CN15.16 L4.2 | length 4951.5
  TopLayer w5: CN15.15@3780,1120 CN15.15@3800,1100
  TopLayer w12: L4.2@1050,1327.5 v3(1050,1375) ; C100.2@3575,1120 3780,1120 CN15.15@3800,1100 CN15.16@3900,1100
  BottomLayer w12: v3(1050,1375) 1275,1150 1575,1150 1700,1025 1700,550 2115,135 3700,135 3810,245 3810,1100 CN15.16@3900,1100
NetLD1_2: LD1.2 R317.2 | length 151.1
  TopLayer w5: LD1.2@2250,552.5 2250,575 2325,650 R317.2@2325,672.5
NetLD2_2: LD2.2 R306.2 | length 382.1
  TopLayer w5: LD2.2@2150,552.5 2175,552.5 2275,652.5 2275,775 2325,825 R306.2@2325,847.5
NetLD3_2: LD3.2 R325.2 | length 249.7
  TopLayer w5: LD3.2@2050,552.5 2102.5,552.5 2222.5,672.5 R325.2@2250,672.5
NetLD4_2: LD4.2 R305.2 | length 494
  TopLayer w5: LD4.2@1950,552.5 2002.5,552.5 2025,575 2100,575 2225,700 2225,775 2250,800 R305.2@2250,847.5
NetLD8_2: LD8.2 R236.2 | length 117.5
  TopLayer w5: R236.2@3477.5,2775 LD8.2@3477.5,2892.5
NetLD8_3: LD8.3 R239.2 | length 239.6
  TopLayer w5: LD8.3@3420.47,2890.94 3420.47,2854.53 3450,2825 3450,2725 3477.5,2697.5 R239.2@3477.5,2675
NetLD8_4: LD8.4 R228.1 | length 88.9
  TopLayer w5: LD8.4@3420.47,3009.06 R228.1@3420.47,3097.97
NetOAM1_1: OAM1.1 R113.2 | length 246.8
  TopLayer w5: R113.2@2875,5802.5 2902.5,5802.5 2953.15,5853.15 OAM1.1@2953.15,6000.79
NetOAM1_3: OAM1.3 R84.2 | length 202.7
  TopLayer w5: R84.2@3100,5802.5 3100,5990.16 OAM1.3@3110.63,6000.79
NetOAM1_4: OAM1.4 R116.2 SB2.1 | length 708.5
  TopLayer w5: R116.2@2725,5737.5 2757.5,5737.5 2769,5749 2769,5770 SB2.1@2792,5793 ; SB2.1@2800,5795 2800,5950 2900,6050 3140.16,6050 OAM1.4@3189.37,6000.79
NetOAM1_6: OAM1.6 R77.2 | length 269.5
  TopLayer w5: R77.2@3175,5802.5 3175,5825 3346.85,5996.85 OAM1.6@3346.85,6000.79
NetOAM1_7: 3SA.1 3SA.6 OAM1.7 | length 3175.3
  TopLayer w5: 3SA.6@433.07,5998.43 500,5931.5 500,5868.5 3SA.1@566.93,5801.57
  BottomLayer w5: 3SA.6@433.07,5998.43 484.65,6050 1300,6050 1500,6250 3038.58,6250 OAM1.7@3189.37,6099.21
NetOAM1_9: OAM1.9 R85.1 | length 368.4
  TopLayer w5: R85.1@3250,5802.5 3250,5850 3385,5985 3385,6061.06 OAM1.9@3346.85,6099.21
NetOAM2_1: 3SA.3 3SA.4 OAM2.1 | length 1207.9
  TopLayer w5: 3SA.4@433.07,5801.57 390,5844.65 390,6020 410,6040 525.35,6040 3SA.3@566.93,5998.43
  BottomLayer w5: 3SA.4@433.07,5801.57 433.07,5583.07 400,5550 400,5225 430,5195 507.36,5195 OAM2.1@549.21,5153.15
NetOAM2_3: OAM2.3 R100.2 | length 641.3
  TopLayer w5: OAM2.3@549.21,5310.63 604.84,5255 R100.2@1167.5,5255
NetOAM2_4: OAM2.4 R132.2 SB5.1 | length 953.1
  TopLayer w5: v1(625,5150) 750,5150 760,5140 1134,5140 1227.5,5046.5 R132.2@1227.5,5025
  BottomLayer w5: OAM2.4@549.21,5389.37 575.63,5389.37 625,5340 v1(625,5150)
NetOAM2_6: OAM2.6 R96.2 | length 683.1
  TopLayer w5: OAM2.6@549.21,5546.85 575,5546.85 581.85,5540 1035,5540 R96.2@1172.5,5402.5
NetOAM2_7: OAM2.7 R134.2 | length 919.1
  TopLayer w5: v1(600,5175) 750,5175 775,5150 1000,5150 1025,5175 R134.2@1172.5,5175
  BottomLayer w5: OAM2.7@450.79,5389.37 490.16,5350 575,5350 600,5325 v1(600,5175)
NetOAM2_9: OAM2.9 R92.2 | length 962.1
  TopLayer w5: OAM2.9@450.79,5546.85 498.94,5595 555,5595 595,5555 1045,5555 1150,5450 1275,5450 1300,5475 R92.2@1322.5,5475
NetPGM1_9: PG3SA.1 PG3SA.6 PGM1.9 | length 1021.9
  TopLayer w5: PG3SA.6@2023.43,6141.93 2023.43,6110 2083.43,6050 2175,6050 2275,6150 2610,6150 PGM1.9@2670,6090
  BottomLayer w5: PG3SA.1@1826.57,6008.07 1893.5,6075 1956.5,6075 PG3SA.6@2023.43,6141.93
NetPGM2_3: PG3SA.3 PG3SA.4 PGM2.3 | length 3275.4
  TopLayer w5: PG3SA.4@1826.57,6141.93 1893.5,6075 1956.5,6075 PG3SA.3@2023.43,6008.07
  BottomLayer w5: PGM2.3@549.21,4635.63 509.84,4675 400,4675 290,4785 290,5815 425,5950 600,5950 690,6040 1315,6040 1416.93,6141.93 PG3SA.4@1826.57,6141.93
NetR5_1: CN2.21 R5.1 | length 6725.8
  TopLayer w5: R5.1@2024,3752.5 v1(2051.5,3725)
  BottomLayer w5: v1(2051.5,3725) 2069.19,3707.31 2682.31,3707.31 2785,3810 3290,3810 3380,3720 3380,3345 3485,3240 3680,3240 3770,3330 3770,4106.86 3855,4191.86 3855,5930 3885,5960 3885,6105 3715,6275 3425,6275 3325,6375 2575,6375 2550,6400 2550,6475 CN2.21@2500,6525
NetR7_1: CN2.23 R7.1 | length 6713.5
  TopLayer w5: R7.1@2100,3752.5 v1(2122.5,3730)
  BottomLayer w5: v1(2122.5,3730) 2127.5,3725 2675,3725 2775,3825 3300,3825 3400,3725 3400,3350 3500,3250 3675,3250 3760,3335 3760,4111 3845,4196 3845,5940 3875,5970 3875,6100 3710,6265 3410,6265 3315,6360 2490,6360 2450,6400 2450,6475 CN2.23@2400,6525
NetR9_2: C3.1 R9.2 R67.1 | length 4523.4
  TopLayer w5: R9.2@2725,3752.5 v1(2725,3800) ; R67.1@3625,6122.5 C3.1@3625,6052.5 3647.5,6052.5 3665,6035 v1(3665,5970)
  BottomLayer w5: v1(2725,3800) 2765,3840 3310,3840 3410,3740 3410,3365 3515,3260 3670,3260 3750,3340 3750,4115.15 3835,4200.15 3835,5840 3725,5950 3685,5950 v1(3665,5970)
NetR10_2: R10.2 R158.1 R164.2 | length 2783.9
  TopLayer w12: R10.2@2725,3647.5 2725,3625 2800,3550 3025,3550 v1(3075,3500) ; v1(3925,4450) 3950,4475 R164.2@4200,4475
  BottomLayer w12: v1(3075,3500) 3175,3500 3463,3212 3697.86,3212 3925,3439.14 v1(3925,4450)
NetR11_2: C19.2 CN4.26 R11.2 | length 3691.8
  TopLayer w5: CN4.26@125,4675 250,4675 405,4520 575,4520 610,4555 1080,4555 1150,4625 1275,4625 1300,4650 C19.2@1322.5,4650 1322.5,4627.5 1340,4610 1391.72,4610 1430,4571.72 1430,4195 1590,4035 1590,3735 v1(1600,3725) ; v1@2810,3787.5 v1(2810,3785) 2827.5,3802.5 R11.2@2827.5,3805
  BottomLayer w5: v1(1600,3725) 1650,3675 2700,3675 v1(2810,3785)
NetR12_2: C108.2 R12.2 U27.4 | length 2933.9
  TopLayer w5: U27.4@2575.27,347.33 2625,397.05 2625,775 2575,825 C108.2@2575,847.5 2600,847.5 2640,887.5 2640,1258.43 2705,1323.43 2705,1758.28 2805,1858.28 2805,2068.43 2995,2258.43 v1(2995,2400) ; v1(3100,2750) 3100,2950 3125,2975 R12.2@3125,2997.5
  BottomLayer w5: v1(2995,2400) 2995,2420 3100,2525 v1(3100,2750)
NetR13_1: C14.1 R13.1 R91.1 | length 3342.3
  TopLayer w5: R91.1@1227.5,5475 1250,5475 1322.5,5547.5 C14.1@1322.5,5550 1357.5,5515 1410,5515 1476,5449 1476,4625 1450,4599 1450,4225 1610,4065 1610,3790 1635,3765 v1(1635,3725) ; v1(2760,3760) R13.1@2792.5,3760
  BottomLayer w5: v1@1630,3730 1669.96,3690.04 2690.04,3690.04 v1(2760,3760)
NetR14_1: R14.1 RV2.2 | length 4196.6
  TopLayer w12: R14.1@2800,3647.5 2800,3625 2850,3575 3050,3575 3150,3475 v1(3150,3400)
  BottomLayer w12: v1(3150,3400) 3300,3250 3300,3050 3425,2925 3425,1955 3074.73,1604.73 3074.73,825.27 3625,275 RV2.2@3625,200
NetR15_2: PG3SA.2 PGM1.3 PGM1.6 R15.2 | length 5571.1
  TopLayer w5: PG3SA.2@1925,6008.07 1983.07,5950 2150,5950 2250,6050 2386.42,6050 PGM1.3@2435.63,6000.79 ; R15.2@2772.5,3865 2800,3892.5 2800,4080 2815,4095 v1(2855,4095)
  BottomLayer w5: v1(2145,5950) 2145,5830 2275,5700 2425,5700 2479,5754 3408,5754 3524,5870 3680,5870 3755,5795 3755,4240 3655,4140 3515,4140 3460,4085 2865,4085 v1(2855,4095) ; PGM1.3@2435.63,6000.79 2486.42,5950 2621.06,5950 PGM1.6@2671.85,6000.79
NetR17_2: C28.2 CN4.34 R17.2 | length 2156.9
  TopLayer w5: CN4.34@125,4275 125,4250 375,4000 C28.2@397.5,4000 397.5,4022.5 420,4045 v1(1500,4045) ; v1(1775,4075) 1775,3900 1803,3872 R17.2@1803,3752.5
  BottomLayer w5: v1(1500,4045) 1530,4075 v1(1775,4075)
NetR18_2: R18.2 R265.2 R276.1 T7.2 | length 2718.8
  TopLayer w5: T7.2@890,1662.5 850,1702.5 850,1797.5 877.5,1825 877.5,1900 1025,1900 1075,1950 1200,1950 1225,1975 1225,2225 1315,2315 1315,2615 v1(1375,2675) ; v1(1775,3650) R18.2@1800.5,3650
  BottomLayer w5: v1(1375,2675) 1400,2700 1425,2700 1500,2775 1500,3600 1550,3650 v1(1775,3650)
NetR19_2: C136.1 R19.2 R108.2 R120.1 | length 3031.8
  TopLayer w5: R120.1@1227.5,4800 C136.1@1322.5,4800 ; R108.2@1377.5,5025 1377.5,4992.5 1350,4965 1350,4860 1322.5,4832.5 1322.5,4777.5 1350,4750 1350,4635 1360,4625 1390.86,4625 1440,4575.86 1440,4210 1600,4050 1600,3765 v1(1615,3750) ; v1(2695,3780) 2685,3790 2685,4000 2705,4020 2705,4095 2735,4125 R19.2@2772.5,4125
  BottomLayer w5: v1(1615,3750) 2665,3750 v1(2695,3780)
NetR21_2: C29.2 R21.2 R133.2 R135.2 | length 358.4
  TopLayer w5: R133.2@2827.5,4060 2902.5,4060 2902.5,4102.5 2925,4125 2925,4220 2920,4225 2862.5,4225 R21.2@2827.5,4190
NetR22_2: C122.2 R22.2 U27.3 | length 3101.2
  TopLayer w5: U27.3@2402.67,174.73 2445,217.05 2445,570 2475,600 2475,800 2500,825 C122.2@2500,847.5 2517.5,847.5 2530,860 2530,1001.72 2620,1091.72 2620,1266.72 2685,1331.72 2685,1766.57 2785,1866.57 2785,2076.72 2955,2246.72 v1(2955,2400) ; v1(3050,2950) R22.2@3050,2997.5
  BottomLayer w5: v1(2955,2400) 2955,2430 3050,2525 v1(3050,2950)
NetR23_1: CN2.5 R23.1 | length 3273.4
  TopLayer w5: R23.1@2772.5,4255 2772.5,4277.5 2780,4285 2935,4285 v1(2970,4250) ; CN2.5@3300,6525 3340,6565 3425,6565 3450,6540 3450,6400 3525,6325 3525,5865.15 3415,5755.15 3415,4885 3440,4860 3440,4265 v1(3435,4260)
  BottomLayer w5: v1(2970,4250) 2995,4225 3400,4225 v1(3435,4260)
NetR24_1: R24.1 R317.1 | length 4013.8
  TopLayer w5: R317.1@2325,727.5 2325,800 2346.02,821.02 2346.02,825 2375,853.98 v1(2375,985) ; R24.1@2877.5,4255 2940,4255 2970,4225 3000,4225 3015,4210 3015,4015 2985,3985 2985,3785 2960,3760 2910,3760 v1(2900,3750)
  BottomLayer w5: v1(2375,985) 2395,1005 2395,3015 2635,3255 2737.57,3255 2795,3312.43 2795,3645 v1(2900,3750)
NetR25_1: CN2.3 R25.1 | length 3097.9
  TopLayer w5: R25.1@2772.5,4320 2772.5,4342.5 2780,4350 2920,4350 v1(3015,4255) ; CN2.3@3400,6525 3440,6485 3440,6395 3515,6320 3515,5869.29 3405,5759.29 3405,4870 3430,4845 3430,4280 v1(3410,4260)
  BottomLayer w5: v1(3015,4255) 3035,4235 3385,4235 v1(3410,4260)
NetR26_1: R26.1 R306.1 | length 3914.5
  TopLayer w5: R306.1@2325,902.5 v1(2325,965) ; R26.1@2877.5,4320 2925,4320 3025,4220 3025,4010.86 2995,3980.86 2995,3780 2965,3750 2925,3750 v1(2900,3725)
  BottomLayer w5: v1(2325,965) 2385,965 2405,985 2405,3010 2640,3245 2741.72,3245 2805,3308.28 2805,3630 v1(2900,3725)
NetR27_1: CN2.9 R27.1 | length 3275
  TopLayer w5: v1(2735,4385) R27.1@2772.5,4385 ; CN2.9@3100,6525 3140,6565 3225,6565 3250,6540 3250,6400 3265,6385 3435.86,6385 3505,6315.86 3505,5873.43 3395,5763.43 3395,4855 3420,4830 3420,4455 v1(3400,4435)
  BottomLayer w5: v1(2735,4385) 2980.94,4385 2990,4394.06 3359.06,4394.06 v1(3400,4435)
NetR28_1: R28.1 R325.1 | length 4202.7
  TopLayer w5: R325.1@2250,727.5 2250,775 2285,810 v1(2285,945) ; R28.1@2877.5,4385 2915,4385 3035,4265 3035,4006.72 3005,3976.72 3005,3775 2970,3740 2940,3740 v1(2925,3725)
  BottomLayer w5: v1(2285,945) 2380.86,945 2415,979.14 2415,3005 2645,3235 2745.86,3235 2815,3304.14 2815,3615 v1(2925,3725)
NetR29_1: CN2.7 R29.1 | length 3006.3
  TopLayer w5: R29.1@2772.5,4450 2797.5,4425 2900,4425 v1(2920.94,4404.06) ; CN2.7@3200,6525 3240,6485 3240,6395 3260,6375 3431.72,6375 3495,6311.72 3495,5877.57 3385,5767.57 3385,4840 3400,4825 v1(3400,4475)
  BottomLayer w5: v1(2920.94,4404.06) 3339.06,4404.06 3400,4465 v1(3400,4475)
NetR30_1: R30.1 R305.1 | length 4114.6
  TopLayer w5: R305.1@2250,902.5 v1(2250,925) ; R30.1@2877.5,4450 2920,4450 2940,4430 2940,4395 3045,4290 3045,4002.57 3015,3972.57 3015,3770 2975,3730 2955,3730 v1(2925,3700)
  BottomLayer w5: v1(2250,925) 2375,925 2425,975 2425,3000 2650,3225 2750,3225 2825,3300 2825,3600 v1(2925,3700)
